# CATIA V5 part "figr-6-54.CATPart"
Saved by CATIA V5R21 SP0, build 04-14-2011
Part number: Part1
Bounding box of the stored display mesh (mm): x -50.648 to 50.648, y -72.183 to 72.183, z 0 to 52
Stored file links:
  D:\CATIA V5R21 E-RESOURCES\CATIA-V5R21\catia-v5r21-prt\c06-catia-v5r21-prt\c06-catia-v5r21-figr-6-54.CATPart
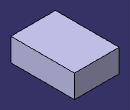
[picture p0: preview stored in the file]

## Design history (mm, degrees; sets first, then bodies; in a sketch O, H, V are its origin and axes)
Body1 (main body)
  Sketch1 on xy-plane, origin (0, 0, 0), H (1, 0, 0), V (0, 1, 0)
    line L1 (-50.6478, 72.1832) -> (50.6478, 72.1832)
    line L2 (50.6478, 72.1832) -> (50.6478, -72.1832)
    line L3 (50.6478, -72.1832) -> (-50.6478, -72.1832)
    line L4 (-50.6478, -72.1832) -> (-50.6478, 72.1832)
    axis line L5 (50.6478, -72.1832) -> (-50.6478, 72.1832)
    horizontal: L1 H, L3 H
    vertical: L2 V, L4 V
    midpoint: O L5
  Pad1: profile Sketch1, direction (0, 0, 1), length 52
